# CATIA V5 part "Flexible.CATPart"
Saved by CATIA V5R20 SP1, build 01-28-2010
Part number: Flexible
Bounding box of the stored display mesh (mm): x -45 to -30, y -27 to 29.079, z 0 to 6
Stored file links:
  F:\Pro\Emplois\1_Chercheur\ThinkMOTION\MMS\MMS_GR1\abruchon\Catia\Flexible.CATPart
  F:\Pro\Emplois\1_Chercheur\ThinkMOTION\MMS\MMS_GR1\abruchon\Catia\Vibrato.CATProduct
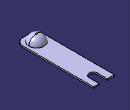
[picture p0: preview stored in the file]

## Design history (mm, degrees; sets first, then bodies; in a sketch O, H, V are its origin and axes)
Set1
  Plane1 to Plane3: linked copy from another document
Body1 (main body)
  Sketch1 on xy-plane, origin (0, 0, 0), H (1, 0, 0), V (0, 1, 0)
    line L1 (-30, 29.079) -> (-30, -27)
    line L2 (-30, -27) -> (-45, -27)
    line L3 (-45, -27) -> (-45, 29.079)
    line L4 (-34, 29.079) -> (-34, 22)
    line L5 (-40, 29.079) -> (-40, 22)
    arc A1 centre (-37, 22) radius 3 from (-34, 22) to (-40, 22) cw
    point P10 (-40, 22)
    line L6 (-34, 29.079) -> (-30, 29.079)
    line L7 (-40, 29.079) -> (-45, 29.079)
    distance L5 L3 = 5
    length L5 = 7.079
    length L4 = 7.079
    distance L7 L6 = 0
    radius A1 = 3
    length L3 = 56.079
    horizontal: L2 H, L6 H, L7 H
    vertical: L1 V, L3 V, L4 V, L5 V
    coincidence: A1 P10, P10 L5
  Pad1: profile Sketch1, direction (0, 0, 1), length 1
  Sketch2 on start face of Pad1, origin (0, 0, 0), H (1, 0, 0), V (0, -1, 0)
    circle A1 centre (-37.5, 19.5) radius 5.5
    reference projected line E1 (-45, -29.079) -> (-45, 27) from edge [start face of Pad1 | face of Pad1 from Sketch1.L3]
    reference projected line E2 (-45, 27) -> (-30, 27) from edge [start face of Pad1 | face of Pad1 from Sketch1.L2]
    reference projected line E3 (-30, 27) -> (-30, -29.079) from edge [start face of Pad1 | face of Pad1 from Sketch1.L1]
    distance A1 E1 = 2
    distance A1 E2 = 2
    distance E3 A1 = 2
  Pad2: profile Sketch2, direction (0, 0, 1), length 6
  Fillet1: radius 5, on edge [face of Pad1 from Sketch1.L2 | face of Pad1 from Sketch1.L3]
  Fillet2: radius 5, on edge [face of Pad1 from Sketch1.L1 | face of Pad1 from Sketch1.L2]
  Fillet3: radius 5, on edge [end face of Pad2 | face of Pad2 from Sketch2.A1]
